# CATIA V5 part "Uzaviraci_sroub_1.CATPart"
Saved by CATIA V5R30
Part number: Uzaviraci_sroub_1
Definition: E 2075_8_12_1
Nomenclature: E 2075_8_12_1
Source: Unknown
Description: PART-E 2075_8_12_1-DESC
Bounding box of the stored display mesh (mm): x -6 to 6, y -6 to 6, z -8 to 0
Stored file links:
  E:\Bakalarka\Model\Forma_v7\Uzaviraci_sroub_1.CATPart
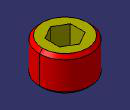
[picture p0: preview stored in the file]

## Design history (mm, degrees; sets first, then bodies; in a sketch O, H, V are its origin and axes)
Body1 "E 2075_8_12" (main body)
  Solid1: solid without history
